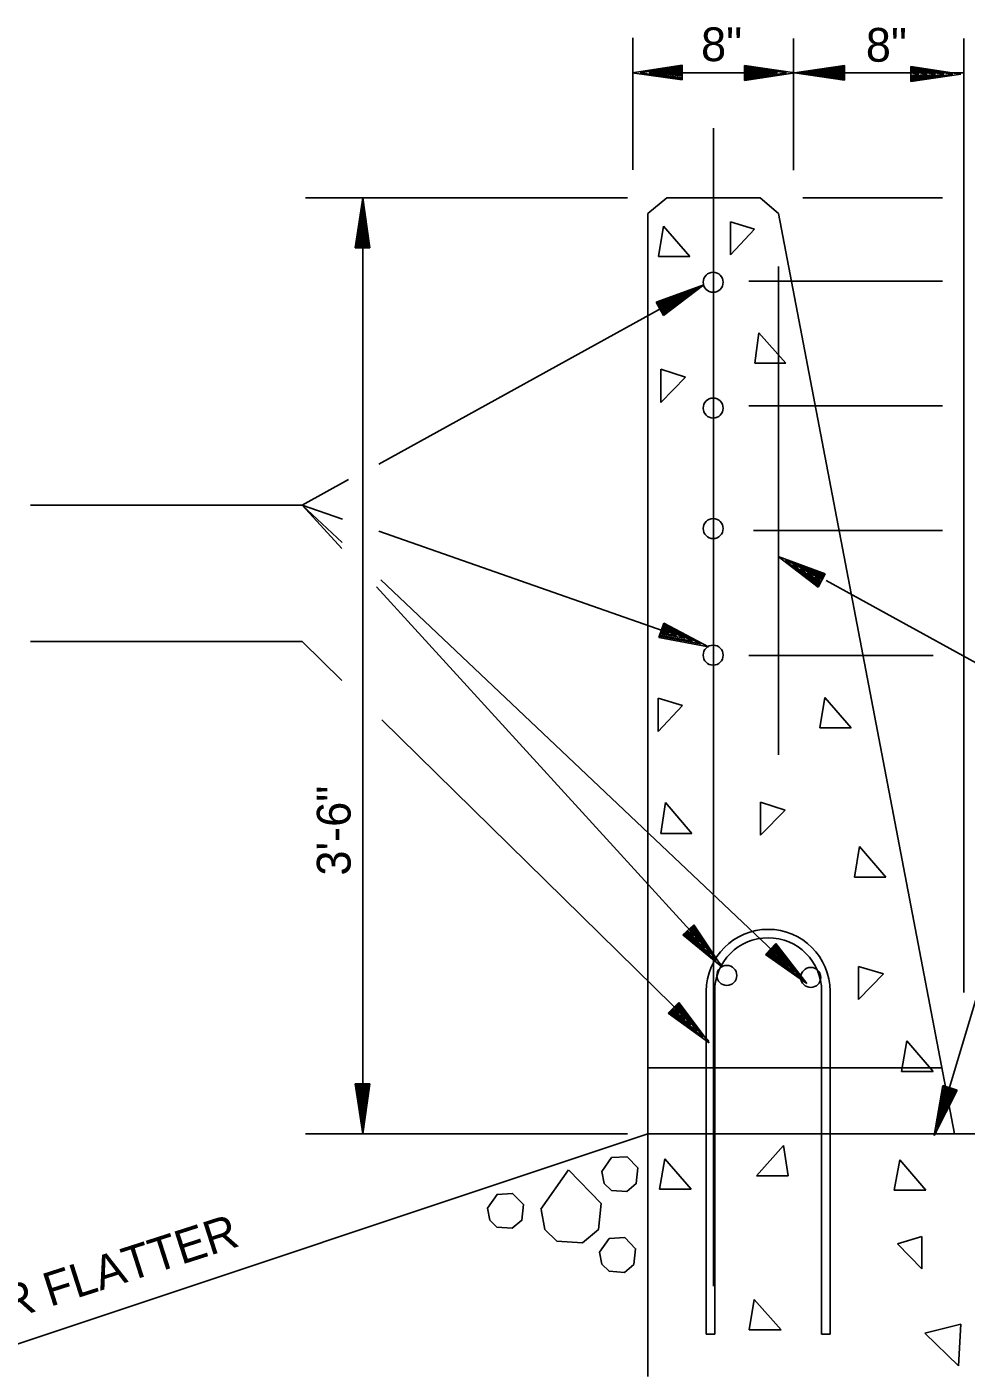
# Model space of a CAD drawing. Extents: x 714919 to 718439, y 1619644 to 1621844.
# Drawn here: x 717627.5 to 717916.1, y 1620506.3 to 1620919.2 of the extents above; entities that cross this region are included whole.
import ezdxf

# ---------------------------------------------------------------- set-up
doc = ezdxf.new("R2010")
doc.units = 0
for name, color, linetype in [('R_Annotation', 7, 'Continuous'), ('R_Centerline', 7, 'Continuous'), ('R_Dimension', 7, 'Continuous'), ('T_Drafting', 7, 'Continuous')]:
    doc.layers.add(name, color=color, linetype=linetype)

msp = doc.modelspace()

# ---------------------------------------------------------------- linework, layer by layer
at = {"layer": 'R_Annotation'}
for p, q in [((717835.49, 1620840.02), (717735.6, 1620784.87)), ((717820.89, 1620834.66), (717835.49, 1620840.02)), ((717821.15, 1620834.4), (717833.24, 1620838.81)), ((717821.32, 1620833.97), (717830.91, 1620837.51)), ((717822.79, 1620831.29), (717830.91, 1620837.51)), ((717822.96, 1620830.94), (717833.24, 1620838.81)), ((717823.13, 1620830.6), (717835.49, 1620840.02)), ((717820.89, 1620834.66), (717823.13, 1620830.6)), ((717821.49, 1620833.62), (717828.66, 1620836.3)), ((717821.67, 1620833.28), (717826.42, 1620835)), ((717821.84, 1620833.02), (717824.08, 1620833.79)), ((717822.18, 1620832.33), (717824.08, 1620833.79)), ((717822.36, 1620831.98), (717826.42, 1620835)), ((717822.62, 1620831.63), (717828.66, 1620836.3)), ((717726.37, 1620780.14), (717712.11, 1620772.28)), ((717638.6, 1620772.28), (717628.68, 1620772.28)), ((717712.11, 1620772.28), (717637.52, 1620772.28)), ((717724.47, 1620767.96), (717712.11, 1620772.28)), ((717712.11, 1620772.28), (717724.26, 1620758.96)), ((717712.11, 1620772.28), (717724.41, 1620760.88)), ((717822.96, 1620733.74), (717735.63, 1620764.34)), ((717872.8, 1620751.18), (717858.29, 1620756.54)), ((717870.64, 1620747.12), (717858.29, 1620756.54)), ((717872.54, 1620750.84), (717860.45, 1620755.33)), ((717870.73, 1620747.47), (717860.45, 1620755.33)), ((717870.99, 1620747.81), (717862.78, 1620754.03)), ((717872.46, 1620750.49), (717862.78, 1620754.03)), ((717872.2, 1620750.15), (717865.11, 1620752.74)), ((717871.16, 1620748.16), (717865.11, 1620752.74)), ((717871.33, 1620748.5), (717867.27, 1620751.53)), ((717872.02, 1620749.8), (717867.27, 1620751.53)), ((717872.8, 1620751.18), (717870.64, 1620747.12)), ((717734.97, 1620747.23), (717840.97, 1620631.08)), ((717736.29, 1620749.37), (717866.51, 1620626.09)), ((717871.51, 1620748.85), (717869.6, 1620750.32)), ((717871.94, 1620749.45), (717869.6, 1620750.32)), ((717873.06, 1620749.11), (717949.7, 1620706.95)), ((717823.22, 1620736.08), (717821.67, 1620731.67)), ((717822.53, 1620734.18), (717824.78, 1620733.05)), ((717822.7, 1620734.52), (717827.11, 1620732.19)), ((717822.79, 1620734.95), (717829.61, 1620731.41)), ((717822.87, 1620735.3), (717832.03, 1620730.55)), ((717823.05, 1620735.64), (717834.45, 1620729.68)), ((717823.22, 1620736.08), (717836.96, 1620728.82)), ((717638.6, 1620730.42), (717628.68, 1620730.42)), ((717712.11, 1620730.42), (717637.52, 1620730.42)), ((717712.11, 1620730.42), (717724.27, 1620718.47)), ((717821.67, 1620731.67), (717836.96, 1620728.82)), ((717821.84, 1620732.1), (717834.45, 1620729.68)), ((717821.92, 1620732.36), (717832.03, 1620730.55)), ((717822.1, 1620732.79), (717829.61, 1620731.41)), ((717822.18, 1620733.14), (717827.11, 1620732.19)), ((717822.27, 1620733.57), (717824.78, 1620733.05)), ((717736.57, 1620706.38), (717836.98, 1620607.7)), ((717931.87, 1620663.32), (717906.65, 1620579.03)), ((717832.42, 1620643.39), (717829.05, 1620640.31)), ((717832.42, 1620643.39), (717841.06, 1620630.47)), ((717829.05, 1620640.31), (717841.06, 1620630.47)), ((717829.29, 1620640.59), (717839.32, 1620632.39)), ((717829.62, 1620640.71), (717837.58, 1620634.32)), ((717829.86, 1620640.99), (717835.76, 1620636.23)), ((717830.19, 1620641.19), (717834.11, 1620638.17)), ((717830.41, 1620641.56), (717832.38, 1620640)), ((717830.98, 1620642.04), (717832.38, 1620640)), ((717831.22, 1620642.24), (717834.11, 1620638.17)), ((717831.63, 1620642.54), (717835.76, 1620636.23)), ((717831.86, 1620642.82), (717837.58, 1620634.32)), ((717832.18, 1620643.11), (717839.32, 1620632.39)), ((717857.61, 1620637.59), (717854.42, 1620634.25)), ((717855.2, 1620635.13), (717861.46, 1620630.71)), ((717855.49, 1620635.45), (717859.54, 1620632.46)), ((717855.69, 1620635.69), (717857.72, 1620634.28)), ((717856.26, 1620636.25), (717857.72, 1620634.28)), ((717856.46, 1620636.49), (717859.54, 1620632.46)), ((717856.74, 1620636.72), (717861.46, 1620630.71)), ((717857.03, 1620637.04), (717863.29, 1620628.97)), ((717857.32, 1620637.27), (717865.2, 1620627.14)), ((717857.61, 1620637.59), (717867.11, 1620625.4)), ((717854.42, 1620634.25), (717867.11, 1620625.4)), ((717854.71, 1620634.57), (717865.2, 1620627.14)), ((717854.82, 1620634.82), (717863.29, 1620628.97)), ((717827.77, 1620619.53), (717824.58, 1620616.27)), ((717827.02, 1620618.64), (717831.49, 1620612.57)), ((717827.24, 1620618.93), (717833.42, 1620610.75)), ((717827.55, 1620619.24), (717835.26, 1620608.93)), ((717827.77, 1620619.53), (717837.1, 1620607.1)), ((717824.58, 1620616.27), (717837.1, 1620607.1)), ((717824.8, 1620616.56), (717835.26, 1620608.93)), ((717825.12, 1620616.7), (717833.42, 1620610.75)), ((717825.34, 1620616.99), (717831.49, 1620612.57)), ((717825.66, 1620617.21), (717829.74, 1620614.41)), ((717825.87, 1620617.59), (717827.91, 1620616.15)), ((717826.4, 1620618.11), (717827.91, 1620616.15)), ((717826.63, 1620618.32), (717829.74, 1620614.41)), ((717908.96, 1620594.02), (717906.24, 1620578.66)), ((717909.38, 1620593.92), (717907.05, 1620581.17)), ((717909.64, 1620593.75), (717907.85, 1620583.68)), ((717913.33, 1620592.61), (717908.96, 1620594.02)), ((717913.33, 1620592.61), (717906.24, 1620578.66)), ((717912.94, 1620592.63), (717907.05, 1620581.17)), ((717912.6, 1620592.77), (717907.85, 1620583.68)), ((717910.06, 1620593.65), (717908.69, 1620586.1)), ((717912.15, 1620592.95), (717908.69, 1620586.1)), ((717910.4, 1620593.51), (717909.53, 1620588.53)), ((717911.84, 1620593), (717909.53, 1620588.53)), ((717910.74, 1620593.38), (717910.37, 1620590.96)), ((717911.5, 1620593.14), (717910.37, 1620590.96))]:
    msp.add_line(p, q, dxfattribs=at)
at = {"layer": 'R_Centerline'}
msp.add_line((717838.43, 1620888.14), (717838.43, 1620532.35), dxfattribs=at)
at = {"layer": 'R_Dimension'}
for p, q in [((717813.63, 1620915.87), (717813.63, 1620875.35)), ((717863.05, 1620915.7), (717863.05, 1620875.18)), ((717915.32, 1620915.7), (717915.32, 1620622.55)), ((717828.84, 1620907.49), (717813.46, 1620905.16)), ((717828.84, 1620902.91), (717813.46, 1620905.16)), ((717828.84, 1620907.06), (717815.96, 1620905.16)), ((717828.84, 1620903.26), (717815.96, 1620905.16)), ((717828.84, 1620906.72), (717818.73, 1620905.16)), ((717828.84, 1620903.61), (717818.73, 1620905.16)), ((717819.25, 1620905.07), (717857.52, 1620905.07)), ((717828.84, 1620906.37), (717821.23, 1620905.16)), ((717828.84, 1620904.04), (717821.23, 1620905.16)), ((717828.84, 1620905.94), (717823.83, 1620905.16)), ((717828.84, 1620904.38), (717823.83, 1620905.16)), ((717828.84, 1620905.59), (717826.33, 1620905.16)), ((717828.84, 1620904.82), (717826.33, 1620905.16)), ((717828.84, 1620902.91), (717828.84, 1620907.49)), ((717848.02, 1620907.32), (717863.4, 1620905.07)), ((717848.02, 1620907.32), (717848.02, 1620902.74)), ((717848.02, 1620906.98), (717860.89, 1620905.07)), ((717848.02, 1620906.54), (717858.13, 1620905.07)), ((717848.02, 1620906.2), (717855.62, 1620905.07)), ((717848.02, 1620905.85), (717853.03, 1620905.07)), ((717848.02, 1620905.42), (717850.52, 1620905.07)), ((717848.02, 1620902.74), (717863.4, 1620905.07)), ((717848.02, 1620904.3), (717853.03, 1620905.07)), ((717848.02, 1620903.52), (717858.13, 1620905.07)), ((717848.02, 1620903.09), (717860.89, 1620905.07)), ((717848.02, 1620903.87), (717855.62, 1620905.07)), ((717848.02, 1620904.64), (717850.52, 1620905.07)), ((717863.05, 1620905.07), (717915.32, 1620905.07)), ((717878.69, 1620907.41), (717863.31, 1620905.07)), ((717878.69, 1620902.83), (717863.31, 1620905.07)), ((717878.69, 1620907.06), (717865.82, 1620905.07)), ((717878.69, 1620903.17), (717865.82, 1620905.07)), ((717878.69, 1620906.63), (717868.49, 1620905.07)), ((717878.69, 1620903.61), (717868.49, 1620905.07)), ((717878.69, 1620906.28), (717871.09, 1620905.07)), ((717878.69, 1620903.95), (717871.09, 1620905.07)), ((717878.69, 1620905.85), (717873.68, 1620905.07)), ((717878.69, 1620904.3), (717873.68, 1620905.07)), ((717878.69, 1620905.51), (717876.18, 1620905.07)), ((717878.69, 1620904.73), (717876.18, 1620905.07)), ((717878.69, 1620902.83), (717878.69, 1620907.41)), ((717899.08, 1620907.06), (717914.46, 1620904.73)), ((717899.08, 1620907.06), (717899.08, 1620902.4)), ((717899.08, 1620906.63), (717911.95, 1620904.73)), ((717899.08, 1620906.28), (717909.19, 1620904.73)), ((717899.08, 1620905.85), (717906.68, 1620904.73)), ((717899.08, 1620905.51), (717904.09, 1620904.73)), ((717899.08, 1620905.07), (717901.59, 1620904.73)), ((717899.08, 1620902.4), (717914.46, 1620904.73)), ((717899.08, 1620903.95), (717904.09, 1620904.73)), ((717899.08, 1620903.17), (717909.19, 1620904.73)), ((717899.08, 1620902.83), (717911.95, 1620904.73)), ((717899.08, 1620903.61), (717906.68, 1620904.73)), ((717899.08, 1620904.3), (717901.59, 1620904.73)), ((717713.15, 1620866.71), (717748.23, 1620866.71)), ((717728.35, 1620851.33), (717730.69, 1620866.71)), ((717730.69, 1620866.71), (717730.69, 1620694.69)), ((717732.93, 1620851.33), (717730.69, 1620866.71)), ((717748.23, 1620866.71), (717811.99, 1620866.71)), ((717865.9, 1620866.71), (717908.84, 1620866.71)), ((717728.79, 1620851.33), (717730.69, 1620864.21)), ((717732.59, 1620851.33), (717730.69, 1620864.21)), ((717729.13, 1620851.33), (717730.69, 1620861.44)), ((717729.48, 1620851.33), (717730.69, 1620858.94)), ((717732.15, 1620851.33), (717730.69, 1620861.44)), ((717731.81, 1620851.33), (717730.69, 1620858.94)), ((717729.91, 1620851.33), (717730.69, 1620856.35)), ((717731.46, 1620851.33), (717730.69, 1620856.35)), ((717728.35, 1620851.33), (717732.93, 1620851.33)), ((717730.25, 1620851.33), (717730.69, 1620853.84)), ((717731.03, 1620851.33), (717730.69, 1620853.84)), ((717858.47, 1620845.63), (717858.47, 1620695.64)), ((717849.31, 1620841.14), (717908.84, 1620841.14)), ((717849.31, 1620802.86), (717908.84, 1620802.86)), ((717850.7, 1620764.5), (717862.27, 1620764.5)), ((717857.18, 1620764.5), (717908.84, 1620764.5)), ((717849.31, 1620726.14), (717860.98, 1620726.14)), ((717860.37, 1620726.14), (717905.99, 1620726.14)), ((717730.69, 1620694.69), (717730.69, 1620579.17)), ((717728.35, 1620594.55), (717730.69, 1620579.17)), ((717732.93, 1620594.55), (717728.35, 1620594.55)), ((717728.35, 1620594.55), (717730.69, 1620579.17)), ((717732.93, 1620594.55), (717728.35, 1620594.55)), ((717728.79, 1620594.55), (717730.69, 1620581.77)), ((717728.79, 1620594.55), (717730.69, 1620581.77)), ((717729.13, 1620594.55), (717730.69, 1620584.44)), ((717729.13, 1620594.55), (717730.69, 1620584.44)), ((717729.48, 1620594.55), (717730.69, 1620586.95)), ((717729.48, 1620594.55), (717730.69, 1620586.95)), ((717729.91, 1620594.55), (717730.69, 1620589.54)), ((717729.91, 1620594.55), (717730.69, 1620589.54)), ((717730.25, 1620594.55), (717730.69, 1620592.05)), ((717730.25, 1620594.55), (717730.69, 1620592.05)), ((717732.93, 1620594.55), (717730.69, 1620579.17)), ((717731.46, 1620594.55), (717730.69, 1620589.54)), ((717732.15, 1620594.55), (717730.69, 1620584.44)), ((717732.59, 1620594.55), (717730.69, 1620581.77)), ((717731.81, 1620594.55), (717730.69, 1620586.95)), ((717731.03, 1620594.55), (717730.69, 1620592.05)), ((717732.93, 1620594.55), (717730.69, 1620579.17)), ((717731.46, 1620594.55), (717730.69, 1620589.54)), ((717732.15, 1620594.55), (717730.69, 1620584.44)), ((717732.59, 1620594.55), (717730.69, 1620581.77)), ((717731.81, 1620594.55), (717730.69, 1620586.95)), ((717731.03, 1620594.55), (717730.69, 1620592.05)), ((717713.15, 1620579.17), (717748.23, 1620579.17)), ((717748.23, 1620579.17), (717811.99, 1620579.17))]:
    msp.add_line(p, q, dxfattribs=at)
at = {"layer": 'T_Drafting'}
for p, q in [((717818.3, 1620861.87), (717824.08, 1620866.71)), ((717824.08, 1620866.71), (717852.77, 1620866.71)), ((717858.47, 1620861.87), (717852.77, 1620866.71)), ((717818.3, 1620861.87), (717818.3, 1620579.17)), ((717843.67, 1620849.17), (717843.67, 1620859.37)), ((717843.67, 1620859.37), (717851.1, 1620857.12)), ((717858.47, 1620861.87), (717912.47, 1620579.17)), ((717823.1, 1620857.99), (717821.55, 1620848.65)), ((717831.22, 1620848.65), (717823.1, 1620857.99)), ((717851.1, 1620857.12), (717843.67, 1620849.17)), ((717821.55, 1620848.65), (717831.22, 1620848.65)), ((717852.36, 1620825.24), (717851.16, 1620815.91)), ((717860.66, 1620815.91), (717852.36, 1620825.24)), ((717822.3, 1620803.84), (717822.3, 1620814.04)), ((717822.3, 1620814.04), (717829.9, 1620811.62)), ((717851.16, 1620815.91), (717860.66, 1620815.91)), ((717829.9, 1620811.62), (717822.3, 1620803.84)), ((717821.46, 1620702.81), (717821.46, 1620713.01)), ((717821.46, 1620713.01), (717828.89, 1620710.76)), ((717828.89, 1620710.76), (717821.46, 1620702.81)), ((717872.67, 1620713.18), (717871.11, 1620703.85)), ((717880.79, 1620703.85), (717872.67, 1620713.18)), ((717871.11, 1620703.85), (717880.79, 1620703.85)), ((717823.67, 1620680.92), (717822.29, 1620671.42)), ((717831.79, 1620671.42), (717823.67, 1620680.92)), ((717852.88, 1620670.87), (717852.88, 1620681.07)), ((717852.88, 1620681.07), (717860.49, 1620678.65)), ((717860.49, 1620678.65), (717852.88, 1620670.87)), ((717822.29, 1620671.42), (717831.79, 1620671.42)), ((717883.3, 1620667.39), (717881.74, 1620658.06)), ((717891.42, 1620658.06), (717883.3, 1620667.39)), ((717881.74, 1620658.06), (717891.42, 1620658.06)), ((717883.04, 1620620.39), (717883.04, 1620630.58)), ((717883.04, 1620630.58), (717890.64, 1620628.34)), ((717890.64, 1620628.34), (717883.04, 1620620.39)), ((717836.24, 1620622.97), (717836.24, 1620517.6)), ((717838.83, 1620517.6), (717838.83, 1620622.97)), ((717871.69, 1620622.97), (717871.69, 1620517.6)), ((717874.28, 1620517.6), (717874.28, 1620622.97)), ((717897.81, 1620607.69), (717896.26, 1620598.35)), ((717905.93, 1620598.35), (717897.81, 1620607.69)), ((717908.6, 1620599.42), (717818.3, 1620599.42)), ((717896.26, 1620598.35), (717905.93, 1620598.35)), ((717818.3, 1620579.17), (717433.73, 1620450.99)), ((717912.47, 1620579.17), (717818.3, 1620579.17)), ((717818.3, 1620579.17), (717818.3, 1620504.64)), ((718045.57, 1620579.17), (717912.47, 1620579.17)), ((717851.67, 1620566.22), (717859.97, 1620575.54)), ((717859.97, 1620575.54), (717861.35, 1620566.22)), ((717823.47, 1620571.48), (717821.92, 1620562.15)), ((717831.6, 1620562.15), (717823.47, 1620571.48)), ((717895.71, 1620571.22), (717893.98, 1620561.9)), ((717903.66, 1620561.9), (717895.71, 1620571.22)), ((717861.35, 1620566.22), (717851.67, 1620566.22)), ((717821.92, 1620562.15), (717831.6, 1620562.15)), ((717893.98, 1620561.9), (717903.66, 1620561.9)), ((717902.42, 1620547.67), (717895, 1620545.42)), ((717895, 1620545.42), (717902.42, 1620537.65)), ((717902.42, 1620537.65), (717902.42, 1620547.67)), ((717850.95, 1620528.31), (717849.4, 1620518.98)), ((717859.25, 1620518.98), (717850.95, 1620528.31)), ((717903.37, 1620517.94), (717914.43, 1620520.71)), ((717914.43, 1620520.71), (717913.74, 1620507.92)), ((717836.24, 1620517.6), (717838.83, 1620517.6)), ((717849.4, 1620518.98), (717859.25, 1620518.98)), ((717874.28, 1620517.6), (717871.69, 1620517.6)), ((717913.74, 1620507.92), (717903.37, 1620517.94))]:
    msp.add_line(p, q, dxfattribs=at)
for points in [[(717804.18, 1620567.62), (717807.16, 1620571.86), (717811.92, 1620572.13), (717815.22, 1620568.7), (717814.75, 1620563.9), (717811.81, 1620561.45), (717807.11, 1620561.79), (717804.9, 1620563.94), (717804.18, 1620567.62)], [(717785.44, 1620556.05), (717793.94, 1620568.14)], [(717793.99, 1620568.04), (717803.91, 1620557.75), (717803.11, 1620549.74), (717798.21, 1620545.67), (717790.38, 1620546.23), (717786.69, 1620549.81), (717785.5, 1620555.95)], [(717769.01, 1620556.34), (717771.99, 1620560.58), (717776.75, 1620560.85), (717780.06, 1620557.42), (717779.58, 1620552.61), (717776.64, 1620550.17), (717771.94, 1620550.51), (717769.73, 1620552.65), (717769.02, 1620556.34)], [(717803.46, 1620542.8), (717806.44, 1620547.04), (717811.2, 1620547.31), (717814.51, 1620543.88), (717814.03, 1620539.07), (717811.09, 1620536.62), (717806.39, 1620536.96), (717804.18, 1620539.11), (717803.46, 1620542.79)]]:
    msp.add_lwpolyline(points, dxfattribs=at)
for centre in [(717838.36, 1620840.77), (717838.36, 1620802.13), (717838.36, 1620765.1), (717838.36, 1620726.23), (717842.55, 1620627.83), (717868.34, 1620627.21)]:
    msp.add_circle(centre, 3.07, dxfattribs=at)
for radius in [19.02, 16.43]:
    msp.add_arc((717855.26, 1620622.97), radius, 0, 180, dxfattribs=at)

# ---------------------------------------------------------------- texts
at = {"layer": 'R_Annotation'}
msp.add_text('3:1 OR FLATTER', height=10.3685, rotation=17.7859, dxfattribs=at).set_placement((717589.14, 1620511.4))
at = {"layer": 'R_Dimension'}
for p in [(717834.63, 1620908.7), (717885.26, 1620908.53)]:
    msp.add_text('8"', height=10.369, dxfattribs=at).set_placement(p)
msp.add_text('3\'-6"', height=10.369, rotation=90, dxfattribs=at).set_placement((717726.97, 1620658.5))

doc.saveas('drawing.dxf')
